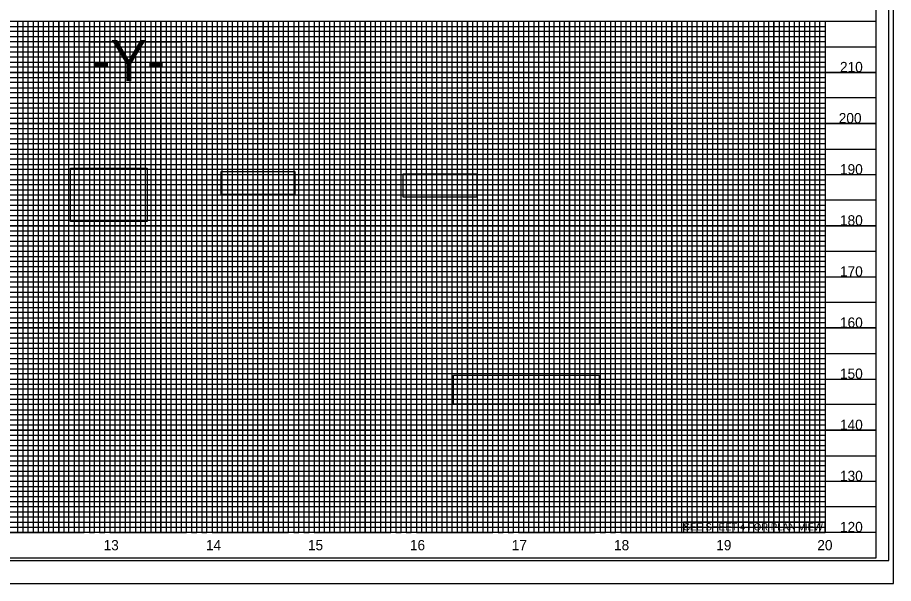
# Model space of a CAD drawing. Extents: x 1779926 to 1781610, y 620464 to 621564.
# Drawn here: x 1780753 to 1781610, y 620464 to 621018 of the extents above; entities that cross this region are included whole.
import ezdxf

# ---------------------------------------------------------------- set-up
doc = ezdxf.new("R2010")
doc.units = 0
for name, color, linetype in [('Exist Vertical Profile Horizontal Axis Label Major', 7, 'Continuous'), ('Exist Vertical Profile Vertical Axis Label', 7, 'Continuous'), ('Prop DSN Text', 7, 'Continuous'), ('Prop Grid Mask', 7, 'Continuous'), ('Scratch_Level_0', 7, 'Continuous'), ('Sheet Cutting Line CELL', 7, 'Continuous'), ('Sheet DOT Grid CELL', 7, 'Continuous'), ('Sheet Layout Profile Border Port 2', 7, 'Continuous'), ('Sheet Plot Border Inside CELL', 7, 'Continuous'), ('Sheet Plot Border Outside CELL', 7, 'Continuous'), ('Sheet Profile CELL', 7, 'Continuous'), ('Sheet Profile Grid Major CELL', 7, 'Continuous'), ('Sheet Profile Grid Middle CELL', 7, 'Continuous'), ('Sheet Profile Grid Minor CELL', 7, 'Continuous')]:
    doc.layers.add(name, color=color, linetype=linetype)

msp = doc.modelspace()

# ---------------------------------------------------------------- linework, layer by layer
at = {"layer": 'Prop Grid Mask'}
for points in [[(1780822.96, 620994.19), (1780912.96, 620994.19), (1780912.96, 620954.19), (1780822.96, 620954.19)], [(1780804.38, 620870.35), (1780879.56, 620870.35), (1780879.56, 620818.3), (1780804.38, 620818.3)], [(1780951.8, 620867.29), (1781023.89, 620867.29), (1781023.89, 620844.67), (1780951.8, 620844.67)], [(1781129.98, 620864.83), (1781202.07, 620864.83), (1781202.07, 620842.21), (1781129.98, 620842.21)], [(1781179.3, 620668.02), (1781321.82, 620668.02), (1781321.82, 620639.74), (1781179.3, 620639.74)], [(1781542.96, 620524.19), (1781404.46, 620524.19), (1781404.46, 620514.19), (1781542.96, 620514.19)]]:
    msp.add_lwpolyline(points, close=True, dxfattribs=at)
at = {"layer": 'Scratch_Level_0'}
msp.add_lwpolyline([(1780142.96, 620514.19), (1780142.96, 621014.19), (1781542.96, 621014.19), (1781542.96, 620514.19)], close=True, dxfattribs=at)
at = {"layer": 'Sheet Cutting Line CELL'}
msp.add_line((1779925.96, 620464.19), (1781609.96, 620464.19), dxfattribs=at)
at = {"layer": 'Sheet DOT Grid CELL'}
for p, q in [((1780092.96, 621014.19), (1781592.85, 621014.19)), ((1780792.96, 621014.19), (1780792.96, 620514.19)), ((1780842.96, 621014.19), (1780842.96, 620514.19)), ((1780892.96, 621014.19), (1780892.96, 620514.19)), ((1780942.96, 621014.19), (1780942.96, 620514.19)), ((1780992.96, 621014.19), (1780992.96, 620514.19)), ((1781042.96, 621014.19), (1781042.96, 620514.19)), ((1781092.96, 621014.19), (1781092.96, 620514.19)), ((1781142.96, 621014.19), (1781142.96, 620514.19)), ((1781192.96, 621014.19), (1781192.96, 620514.19)), ((1781242.96, 621014.19), (1781242.96, 620514.19)), ((1781292.96, 621014.19), (1781292.96, 620514.19)), ((1781342.96, 621014.19), (1781342.96, 620514.19)), ((1781392.96, 621014.19), (1781392.96, 620514.19)), ((1781442.96, 621014.19), (1781442.96, 620514.19)), ((1781492.96, 621014.19), (1781492.96, 620514.19)), ((1781542.96, 621014.19), (1781542.96, 620514.19)), ((1780092.96, 620964.19), (1781592.85, 620964.19)), ((1780092.96, 620914.19), (1781592.85, 620914.19)), ((1780092.96, 620864.19), (1781592.85, 620864.19)), ((1780092.96, 620814.19), (1781592.85, 620814.19)), ((1780092.96, 620764.19), (1781592.85, 620764.19)), ((1780092.96, 620714.19), (1781592.85, 620714.19)), ((1780092.96, 620664.19), (1781592.85, 620664.19)), ((1780092.96, 620614.19), (1781592.85, 620614.19)), ((1780092.96, 620564.19), (1781592.85, 620564.19))]:
    msp.add_line(p, q, dxfattribs=at)
at = {"layer": 'Sheet Layout Profile Border Port 2'}
for points in [[(1780142.96, 621014.19), (1781542.96, 621014.19), (1781542.96, 620514.19), (1780142.96, 620514.19)], [(1780142.96, 621014.19), (1781382.96, 621014.19), (1781382.96, 620514.19), (1780142.96, 620514.19)]]:
    msp.add_lwpolyline(points, close=True, dxfattribs=at)
at = {"layer": 'Sheet Plot Border Inside CELL'}
msp.add_lwpolyline([(1779938.96, 620486.64), (1781605.46, 620486.64), (1781605.46, 621541.74), (1779938.96, 621541.74)], close=True, dxfattribs=at)
at = {"layer": 'Sheet Plot Border Outside CELL'}
msp.add_lwpolyline([(1779925.96, 620464.19), (1781609.96, 620464.19), (1781609.96, 621564.19), (1779925.96, 621564.19)], close=True, dxfattribs=at)
at = {"layer": 'Sheet Profile CELL'}
for p, q in [((1780092.96, 621014.19), (1781592.96, 621014.19)), ((1781592.96, 620514.19), (1780092.96, 620514.19)), ((1780092.96, 620489.19), (1781592.96, 620489.19))]:
    msp.add_line(p, q, dxfattribs=at)
msp.add_lwpolyline([(1781592.96, 621539.19), (1780092.96, 621539.19), (1780092.96, 620489.19), (1781592.96, 620489.19)], close=True, dxfattribs=at)
at = {"layer": 'Sheet Profile Grid Major CELL'}
for p, q in [((1780792.96, 621014.19), (1780842.96, 621014.19)), ((1780892.96, 621014.19), (1780942.96, 621014.19)), ((1780992.96, 621014.19), (1781042.96, 621014.19)), ((1781092.96, 621014.19), (1781142.96, 621014.19)), ((1781192.96, 621014.19), (1781242.96, 621014.19)), ((1781292.96, 621014.19), (1781342.96, 621014.19)), ((1781392.96, 621014.19), (1781442.96, 621014.19)), ((1781492.96, 621014.19), (1781542.96, 621014.19)), ((1781492.96, 620514.19), (1781492.96, 620514.19))]:
    msp.add_line(p, q, dxfattribs=at)
for points in [[(1780742.96, 620514.19), (1780792.96, 620514.19), (1780792.96, 621014.19), (1780842.96, 621014.19), (1780842.96, 620514.19), (1780892.96, 620514.19), (1780892.96, 621014.19), (1780942.96, 621014.19), (1780942.96, 620514.19), (1780992.96, 620514.19), (1780992.96, 621014.19), (1781042.96, 621014.19), (1781042.96, 620514.19), (1781092.96, 620514.19), (1781092.96, 621014.19), (1781142.96, 621014.19), (1781142.96, 620514.19), (1781192.96, 620514.19), (1781192.96, 621014.19), (1781242.96, 621014.19), (1781242.96, 620514.19), (1781292.96, 620514.19), (1781292.96, 621014.19), (1781342.96, 621014.19), (1781342.96, 620514.19), (1781392.96, 620514.19), (1781392.96, 621014.19), (1781442.96, 621014.19), (1781442.96, 620514.19), (1781492.96, 620514.19), (1781492.96, 620514.19), (1781492.96, 621014.19), (1781542.96, 621014.19), (1781542.96, 620514.19)], [(1781592.96, 620964.19), (1780092.96, 620964.19)], [(1781592.96, 620914.19), (1780092.96, 620914.19), (1780092.96, 620864.19), (1781592.96, 620864.19)], [(1781592.96, 620814.19), (1780092.96, 620814.19), (1780092.96, 620764.19), (1781592.96, 620764.19)], [(1781592.96, 620714.19), (1780092.96, 620714.19), (1780092.96, 620664.19), (1781592.96, 620664.19)], [(1781592.96, 620614.19), (1780092.96, 620614.19), (1780092.96, 620614.19), (1780092.96, 620564.19), (1781592.96, 620564.19)], [(1781592.96, 620514.19), (1780092.96, 620514.19)]]:
    msp.add_lwpolyline(points, dxfattribs=at)
at = {"layer": 'Sheet Profile Grid Middle CELL'}
for points in [[(1780717.96, 621014.19), (1780767.96, 621014.19), (1780767.96, 620514.19), (1780817.96, 620514.19), (1780817.96, 621014.19), (1780867.96, 621014.19), (1780867.96, 620514.19), (1780917.96, 620514.19), (1780917.96, 621014.19), (1780967.96, 621014.19), (1780967.96, 620514.19), (1781017.96, 620514.19), (1781017.96, 621014.19), (1781067.96, 621014.19), (1781067.96, 620514.19), (1781117.96, 620514.19), (1781117.96, 621014.19), (1781167.96, 621014.19), (1781167.96, 620514.19), (1781217.96, 620514.19), (1781217.96, 621014.19), (1781267.96, 621014.19), (1781267.96, 620514.19), (1781317.96, 620514.19), (1781317.96, 621014.19), (1781367.96, 621014.19), (1781367.96, 620514.19), (1781417.96, 620514.19), (1781417.96, 621014.19), (1781467.96, 621014.19), (1781467.96, 620514.19), (1781517.96, 620514.19), (1781517.96, 621014.19)], [(1780092.96, 620989.19), (1781592.96, 620989.19)], [(1781592.96, 620939.19), (1780092.96, 620939.19), (1780092.96, 620889.19), (1781592.96, 620889.19)], [(1781592.96, 620839.19), (1780092.96, 620839.19), (1780092.96, 620789.19), (1781592.96, 620789.19)], [(1781592.96, 620739.19), (1780092.96, 620739.19), (1780092.96, 620689.19), (1781592.96, 620689.19)], [(1781592.96, 620639.19), (1780092.96, 620639.19), (1780092.96, 620589.19), (1781592.96, 620589.19)], [(1781592.96, 620539.19), (1780092.96, 620539.19)]]:
    msp.add_lwpolyline(points, dxfattribs=at)
at = {"layer": 'Sheet Profile Grid Minor CELL'}
for p, q in [((1780142.96, 621009.19), (1781542.96, 621009.19)), ((1781542.96, 621004.19), (1780142.96, 621004.19)), ((1780142.96, 620999.19), (1781542.96, 620999.19)), ((1781542.96, 620994.19), (1780142.96, 620994.19)), ((1780142.96, 620984.19), (1781542.96, 620984.19)), ((1781542.96, 620979.19), (1780142.96, 620979.19)), ((1780142.96, 620974.19), (1781542.96, 620974.19)), ((1781542.96, 620969.19), (1780142.96, 620969.19)), ((1780142.96, 620959.19), (1781542.96, 620959.19)), ((1781542.96, 620954.19), (1780142.96, 620954.19)), ((1780142.96, 620949.19), (1781542.96, 620949.19)), ((1781542.96, 620944.19), (1780142.96, 620944.19)), ((1780142.96, 620934.19), (1781542.96, 620934.19)), ((1781542.96, 620929.19), (1780142.96, 620929.19)), ((1780142.96, 620924.19), (1781542.96, 620924.19)), ((1781542.96, 620919.19), (1780142.96, 620919.19)), ((1780142.96, 620909.19), (1781542.96, 620909.19)), ((1781542.96, 620904.19), (1780142.96, 620904.19)), ((1780142.96, 620899.19), (1781542.96, 620899.19)), ((1781542.96, 620894.19), (1780142.96, 620894.19)), ((1780142.96, 620884.19), (1781542.96, 620884.19)), ((1781542.96, 620879.19), (1780142.96, 620879.19)), ((1780142.96, 620874.19), (1781542.96, 620874.19)), ((1781542.96, 620869.19), (1780142.96, 620869.19)), ((1780142.96, 620859.19), (1781542.96, 620859.19)), ((1781542.96, 620854.19), (1780142.96, 620854.19)), ((1780142.96, 620849.19), (1781542.96, 620849.19)), ((1781542.96, 620844.19), (1780142.96, 620844.19)), ((1780142.96, 620834.19), (1781542.96, 620834.19)), ((1781542.96, 620829.19), (1780142.96, 620829.19)), ((1780142.96, 620824.19), (1781542.96, 620824.19)), ((1781542.96, 620819.19), (1780142.96, 620819.34)), ((1780142.96, 620809.19), (1781542.96, 620809.19)), ((1781542.96, 620804.19), (1780142.96, 620804.19)), ((1780142.96, 620799.19), (1781542.96, 620799.19)), ((1781542.96, 620794.19), (1780142.96, 620794.19)), ((1780142.96, 620784.19), (1781542.96, 620784.19)), ((1781542.96, 620779.19), (1780142.96, 620779.19)), ((1780142.96, 620774.19), (1781542.96, 620774.19)), ((1781542.96, 620769.19), (1780142.96, 620769.19)), ((1780142.96, 620759.19), (1781542.96, 620759.19)), ((1781542.96, 620754.19), (1780142.96, 620754.19)), ((1780142.96, 620749.19), (1781542.96, 620749.19)), ((1781542.96, 620744.19), (1780142.96, 620744.19)), ((1780142.96, 620734.19), (1781542.96, 620734.19)), ((1781542.96, 620729.19), (1780142.96, 620729.19)), ((1780142.96, 620724.19), (1781542.96, 620724.19)), ((1781542.96, 620719.19), (1780142.96, 620719.19)), ((1780142.96, 620709.19), (1781542.96, 620709.19)), ((1781542.96, 620704.19), (1780142.96, 620704.19)), ((1780142.96, 620699.19), (1781542.96, 620699.19)), ((1781542.96, 620694.19), (1780142.96, 620694.19)), ((1780142.96, 620684.19), (1781542.96, 620684.19)), ((1781542.96, 620679.19), (1780142.96, 620679.19)), ((1780142.96, 620674.19), (1781542.96, 620674.19)), ((1781542.96, 620669.19), (1780142.96, 620669.19)), ((1780142.96, 620659.19), (1781542.96, 620659.19)), ((1781542.96, 620654.19), (1780142.96, 620654.19)), ((1780142.96, 620649.19), (1781542.96, 620649.19)), ((1781542.96, 620644.19), (1780142.96, 620644.19)), ((1780142.96, 620634.19), (1781542.96, 620634.19)), ((1781542.96, 620629.19), (1780142.96, 620629.19)), ((1780142.96, 620624.19), (1781542.96, 620624.19)), ((1781542.96, 620619.19), (1780142.96, 620619.19)), ((1780142.96, 620609.19), (1781542.96, 620609.19)), ((1781542.96, 620604.19), (1780142.96, 620604.19)), ((1780142.96, 620599.19), (1781542.96, 620599.19)), ((1781542.96, 620594.19), (1780142.96, 620594.19)), ((1780142.96, 620584.19), (1781542.96, 620584.19)), ((1781542.96, 620579.19), (1780142.96, 620579.19)), ((1780142.96, 620574.19), (1781542.96, 620574.19)), ((1781542.96, 620569.19), (1780142.96, 620569.19)), ((1780142.96, 620559.19), (1781542.96, 620559.19)), ((1781542.96, 620554.19), (1780142.96, 620554.19)), ((1780142.96, 620549.19), (1781542.96, 620549.19)), ((1781542.96, 620544.19), (1780142.96, 620544.19)), ((1780142.96, 620534.19), (1781542.96, 620534.19)), ((1781542.96, 620529.19), (1780142.96, 620529.19)), ((1780142.96, 620524.19), (1781542.96, 620524.19)), ((1780142.96, 620519.19), (1781542.96, 620519.19)), ((1781542.96, 620519.19), (1781542.96, 620519.19))]:
    msp.add_line(p, q, dxfattribs=at)
for points in [[(1780747.96, 620514.19), (1780752.96, 620514.19), (1780752.96, 621014.19), (1780757.96, 621014.19), (1780757.96, 620514.19), (1780762.96, 620514.19), (1780762.96, 621014.19), (1780772.96, 621014.19), (1780772.96, 620514.19), (1780777.96, 620514.19), (1780777.96, 621014.19), (1780782.96, 621014.19), (1780782.96, 620514.19), (1780787.96, 620514.19), (1780787.96, 621014.19), (1780797.96, 621014.19), (1780797.96, 620514.19), (1780797.96, 620514.19), (1780802.96, 620514.19), (1780802.96, 621014.19), (1780807.96, 621014.19), (1780807.96, 620514.19), (1780812.96, 620514.19), (1780812.96, 621014.19), (1780822.96, 621014.19), (1780822.96, 620514.19), (1780827.96, 620514.19), (1780827.96, 621014.19), (1780832.96, 621014.19), (1780832.96, 620514.19), (1780837.96, 620514.19), (1780837.96, 621014.19), (1780847.96, 621014.19), (1780847.96, 620514.19), (1780852.96, 620514.19), (1780852.96, 621014.19), (1780857.96, 621014.19), (1780857.96, 620514.19), (1780862.96, 620514.19), (1780862.96, 621014.19), (1780872.96, 621014.19), (1780872.96, 620514.19), (1780877.96, 620514.19), (1780877.96, 621014.19), (1780882.96, 621014.19), (1780882.96, 620514.19), (1780887.96, 620514.19), (1780887.96, 621014.19), (1780897.96, 621014.19), (1780897.96, 620514.19), (1780902.96, 620514.19), (1780902.96, 621014.19), (1780907.96, 621014.19), (1780907.96, 620514.19), (1780912.96, 620514.19), (1780912.96, 621014.19), (1780922.96, 621014.19), (1780922.96, 620514.19), (1780927.96, 620514.19), (1780927.96, 621014.19), (1780932.96, 621014.19), (1780932.96, 620514.19), (1780937.96, 620514.19), (1780937.96, 621014.19), (1780947.96, 621014.19), (1780947.96, 620514.19), (1780952.66, 620514.74), (1780952.96, 620514.19), (1780952.96, 621014.19), (1780957.96, 621014.19), (1780957.96, 620514.19), (1780962.96, 620514.19), (1780962.96, 621014.19), (1780972.96, 621014.19), (1780972.96, 620514.19), (1780977.96, 620514.19)], [(1780977.96, 620514.19), (1780977.96, 621014.19), (1780982.96, 621014.19), (1780982.96, 620514.19), (1780987.96, 620514.19), (1780987.96, 621014.19), (1780997.96, 621014.19), (1780997.96, 620514.19), (1781002.96, 620514.19), (1781002.96, 621014.19), (1781007.96, 621014.19), (1781007.96, 620514.19), (1781012.96, 620514.19), (1781012.96, 621014.19), (1781022.96, 621014.19), (1781022.96, 620514.19), (1781027.96, 620514.19), (1781027.96, 621014.19), (1781032.96, 621014.19), (1781032.96, 620514.19), (1781037.96, 620514.19), (1781037.96, 621014.19), (1781047.96, 621014.19), (1781047.96, 620514.19), (1781052.96, 620514.19), (1781052.96, 621014.19), (1781057.96, 621014.19), (1781057.96, 620514.19), (1781062.96, 620514.19), (1781062.96, 621014.19), (1781072.96, 621014.19), (1781072.96, 620514.19), (1781077.96, 620514.19), (1781077.96, 621014.19), (1781082.96, 621014.19), (1781082.96, 620514.19), (1781087.96, 620514.19), (1781087.96, 621014.19), (1781097.96, 621014.19), (1781097.96, 620514.19), (1781102.96, 620514.19), (1781102.96, 621014.19), (1781107.96, 621014.19), (1781107.96, 620514.19), (1781112.96, 620514.19), (1781112.96, 621014.19), (1781122.96, 621014.19), (1781122.96, 620514.19), (1781127.96, 620514.19), (1781127.96, 621014.19), (1781132.96, 621014.19), (1781132.96, 620514.19), (1781137.96, 620514.19), (1781137.96, 621014.19), (1781147.96, 621014.19), (1781147.96, 620514.19), (1781152.96, 620514.19), (1781152.96, 621014.19), (1781157.96, 621014.19), (1781157.96, 620514.19), (1781162.96, 620514.19), (1781162.96, 621014.19), (1781172.96, 621014.19), (1781172.96, 620514.19), (1781177.96, 620514.19), (1781177.96, 621014.19), (1781182.96, 621014.19), (1781182.96, 620514.19), (1781187.96, 620514.19), (1781187.96, 621014.19), (1781197.96, 621014.19), (1781197.96, 620514.19), (1781202.96, 620514.19), (1781202.96, 621014.19), (1781207.96, 621014.19), (1781207.96, 620514.19), (1781212.96, 620514.19), (1781212.96, 621014.19), (1781222.96, 621014.19), (1781222.96, 620514.19), (1781227.96, 620514.19), (1781227.96, 621014.19), (1781232.96, 621014.19), (1781232.96, 620514.19), (1781237.96, 620514.19), (1781237.96, 621014.19), (1781247.96, 621014.19), (1781247.96, 620514.19), (1781252.96, 620514.19), (1781252.96, 621014.19), (1781257.96, 621014.19), (1781257.96, 620514.19), (1781262.96, 620514.19), (1781262.96, 621014.19), (1781272.96, 621014.19), (1781272.96, 620514.19), (1781277.96, 620514.19), (1781277.96, 621014.19), (1781282.96, 621014.19), (1781282.96, 620514.19)], [(1781282.96, 620514.19), (1781287.96, 620514.19), (1781287.96, 621014.19), (1781297.96, 621014.19), (1781297.96, 620514.19), (1781302.96, 620514.19), (1781302.96, 621014.19), (1781307.96, 621014.19), (1781307.96, 620514.19), (1781312.96, 620514.19), (1781312.96, 621014.19), (1781322.96, 621014.19), (1781322.96, 620514.19), (1781327.96, 620514.19), (1781327.96, 621014.19), (1781332.96, 621014.19), (1781332.96, 620514.19), (1781337.96, 620514.19), (1781337.96, 621014.19), (1781347.96, 621014.19), (1781347.96, 620514.19), (1781352.96, 620514.19), (1781352.96, 621014.19), (1781357.96, 621014.19), (1781357.96, 620514.19), (1781362.96, 620514.19), (1781362.96, 621014.19), (1781372.96, 621014.19), (1781372.96, 620514.19), (1781377.96, 620514.19), (1781377.96, 621014.19), (1781382.96, 621014.19), (1781382.96, 620514.19), (1781387.96, 620514.19), (1781387.96, 621014.19), (1781397.96, 621014.19), (1781397.96, 620514.19), (1781402.96, 620514.19), (1781402.96, 621014.19), (1781407.96, 621014.19), (1781407.96, 620514.19), (1781412.96, 620514.19), (1781412.96, 621014.19), (1781422.96, 621014.19), (1781422.96, 620514.19), (1781427.96, 620514.19), (1781427.96, 621014.19), (1781432.96, 621014.19), (1781432.96, 620514.19), (1781437.96, 620514.19), (1781437.96, 621014.19), (1781447.96, 621014.19), (1781447.96, 620514.19), (1781452.96, 620514.19), (1781452.96, 621014.19), (1781457.96, 621014.19), (1781457.96, 620514.19), (1781462.96, 620514.19), (1781462.96, 621014.19), (1781472.96, 621014.19), (1781472.96, 620514.19), (1781477.96, 620514.19), (1781477.96, 621014.19), (1781482.96, 621014.19), (1781482.96, 620514.19), (1781487.96, 620514.19), (1781487.96, 621014.19), (1781497.96, 621014.19), (1781497.96, 620514.19), (1781502.96, 620514.19), (1781502.96, 621014.19), (1781507.96, 621014.19), (1781507.96, 620514.19), (1781512.96, 620514.19), (1781512.96, 621014.19), (1781522.96, 621014.19), (1781522.96, 620514.19), (1781527.96, 620514.19), (1781527.96, 621014.19), (1781532.96, 621014.19), (1781532.96, 620514.19), (1781537.96, 620514.19), (1781537.96, 621014.19), (1781542.96, 621014.19)]]:
    msp.add_lwpolyline(points, dxfattribs=at)

# ---------------------------------------------------------------- texts
at = {"layer": 'Exist Vertical Profile Horizontal Axis Label Major'}
for s, p in [('13', (1780836.83, 620496.69)), ('14', (1780937, 620496.69)), ('15', (1781036.82, 620496.69)), ('16', (1781136.62, 620496.69)), ('17', (1781236.32, 620496.69)), ('18', (1781336.42, 620496.69)), ('19', (1781436.47, 620496.69)), ('20', (1781535.41, 620496.69))]:
    msp.add_text(s, height=10, dxfattribs=at).set_placement(p)
at = {"layer": 'Exist Vertical Profile Vertical Axis Label'}
for s, height, p in [('-Y-', 40, (1780825.81, 620955.78)), ('210', 10, (1781557.59, 620964.44)), ('200', 10, (1781556.39, 620914.44)), ('190', 10, (1781557.59, 620864.44)), ('180', 10, (1781557.59, 620814.44)), ('170', 10, (1781557.59, 620764.44)), ('160', 10, (1781557.59, 620714.44)), ('150', 10, (1781557.59, 620664.44)), ('140', 10, (1781557.59, 620614.44)), ('130', 10, (1781557.59, 620564.44)), ('120', 10, (1781557.59, 620514.44))]:
    msp.add_text(s, height=height, dxfattribs=at).set_placement(p)
at = {"layer": 'Prop DSN Text'}
msp.add_text('SEE SHEET 4 FOR PLAN VIEW', height=7, dxfattribs=at).set_placement((1781404.55, 620516.14))

doc.saveas('drawing.dxf')
